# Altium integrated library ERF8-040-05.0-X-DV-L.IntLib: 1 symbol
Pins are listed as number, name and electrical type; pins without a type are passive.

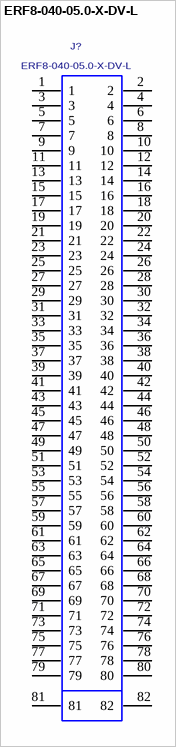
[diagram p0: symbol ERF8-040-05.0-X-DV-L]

## ERF8-040-05.0-X-DV-L
designator J?
0.8mm Edge Rate Socket Assembly, Double Vertical Row, 40 Pins.; MANUFACTURER: SAMTEC
footprint ERF8-040-05.0-X-DV-L
pins: 1, 2, 3, 4, 5, 6, 7, 8, 9, 10, 11, 12, 13, 14, 15, 16, 17, 18, 19, 20, 21, 22, 23, 24, 25, 26, 27, 28, 29, 30, 31, 32, 33, 34, 35, 36, 37, 38, 39, 40, 41, 42, 43, 44, 45, 46, 47, 48, 49, 50, 51, 52, 53, 54, 55, 56, 57, 58, 59, 60, 61, 62, 63, 64, 65, 66, 67, 68, 69, 70, 71, 72, 73, 74, 75, 76, 77, 78, 79, 80, 81, 82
